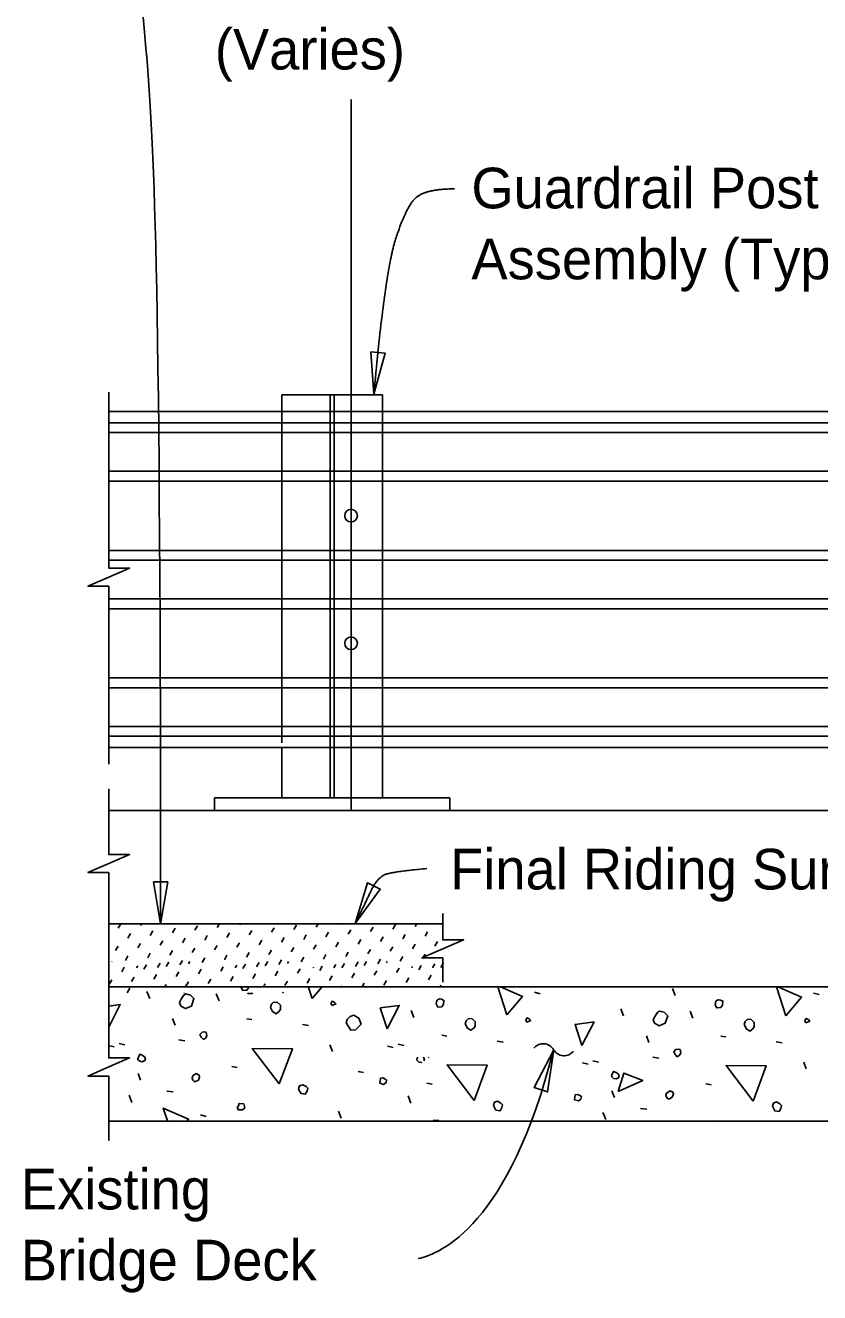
# Model space of a CAD drawing. Extents: x 21526.6 to 21598.7, y 56118.1 to 56155.9.
# Drawn here: x 21526.83 to 21530.77, y 56132.82 to 56139.11 of the extents above; entities that cross this region are included whole.
import ezdxf

# ---------------------------------------------------------------- set-up
doc = ezdxf.new("R2010")
doc.units = 0
for name, color, linetype in [('AdhocPoint_dp', 7, 'Continuous'), ('Border', 7, 'Continuous'), ('Patterning', 7, 'Continuous'), ('PlotBorder_dp', 7, 'Continuous'), ('SheetBorder_dp', 7, 'Continuous'), ('TextMisc', 7, 'Continuous')]:
    doc.layers.add(name, color=color, linetype=linetype)

msp = doc.modelspace()

# ---------------------------------------------------------------- linework, layer by layer
at = {"layer": 'AdhocPoint_dp'}
for p, q in [((21527.2426, 56135.21), (21535.6096, 56135.21)), ((21528.9006, 56134.6484), (21527.2426, 56134.6484)), ((21535.6096, 56134.335), (21527.2426, 56134.335)), ((21527.2426, 56133.6684), (21535.6096, 56133.6684))]:
    msp.add_line(p, q, dxfattribs=at)
at = {"layer": 'Patterning'}
for p, q in [((21528.4455, 56138.7381), (21528.4455, 56135.2123)), ((21527.2896, 56134.6259), (21527.3025, 56134.6483)), ((21527.4002, 56134.6388), (21527.4057, 56134.6484)), ((21527.5597, 56134.603), (21527.5726, 56134.6254)), ((21527.6703, 56134.6159), (21527.6833, 56134.6383)), ((21527.7809, 56134.6289), (21527.7922, 56134.6484)), ((21527.8916, 56134.6419), (21527.8953, 56134.6484)), ((21528.051, 56134.606), (21528.064, 56134.6284)), ((21528.1617, 56134.619), (21528.1746, 56134.6413)), ((21528.2723, 56134.6319), (21528.2818, 56134.6484)), ((21528.3829, 56134.6449), (21528.3849, 56134.6484)), ((21528.5424, 56134.609), (21528.5553, 56134.6314)), ((21528.653, 56134.622), (21528.666, 56134.6444)), ((21528.7637, 56134.6349), (21528.7714, 56134.6484)), ((21528.8743, 56134.6479), (21528.8745, 56134.6484)), ((21527.3384, 56134.577), (21527.3514, 56134.5994)), ((21527.449, 56134.59), (21527.462, 56134.6124)), ((21527.4979, 56134.5412), (21527.5108, 56134.5636)), ((21527.6085, 56134.5541), (21527.6215, 56134.5765)), ((21527.7191, 56134.5671), (21527.7321, 56134.5895)), ((21527.8298, 56134.5801), (21527.8427, 56134.6025)), ((21527.9404, 56134.593), (21527.9534, 56134.6154)), ((21527.9892, 56134.5442), (21528.0022, 56134.5666)), ((21528.0999, 56134.5572), (21528.1128, 56134.5795)), ((21528.2105, 56134.5701), (21528.2235, 56134.5925)), ((21528.3211, 56134.5831), (21528.3341, 56134.6055)), ((21528.4318, 56134.596), (21528.4447, 56134.6184)), ((21528.4806, 56134.5472), (21528.4936, 56134.5696)), ((21528.5912, 56134.5602), (21528.6042, 56134.5826)), ((21528.7019, 56134.5731), (21528.7148, 56134.5955)), ((21528.8125, 56134.5861), (21528.8254, 56134.6085)), ((21527.2766, 56134.5152), (21527.2896, 56134.5376)), ((21527.3872, 56134.5282), (21527.4002, 56134.5506)), ((21527.4361, 56134.4794), (21527.449, 56134.5018)), ((21527.5467, 56134.4923), (21527.5597, 56134.5147)), ((21527.6573, 56134.5053), (21527.6703, 56134.5277)), ((21527.768, 56134.5183), (21527.7809, 56134.5407)), ((21527.8786, 56134.5312), (21527.8916, 56134.5536)), ((21527.9274, 56134.4824), (21527.9404, 56134.5048)), ((21528.0381, 56134.4954), (21528.051, 56134.5177)), ((21528.1487, 56134.5083), (21528.1617, 56134.5307)), ((21528.2593, 56134.5213), (21528.2723, 56134.5437)), ((21528.37, 56134.5342), (21528.3829, 56134.5566)), ((21528.4188, 56134.4854), (21528.4318, 56134.5078)), ((21528.5294, 56134.4984), (21528.5424, 56134.5208)), ((21528.6401, 56134.5113), (21528.653, 56134.5337)), ((21528.7507, 56134.5243), (21528.7637, 56134.5467)), ((21528.8613, 56134.5373), (21528.8743, 56134.5597)), ((21527.2583, 56134.4585), (21527.2592, 56134.46)), ((21527.3254, 56134.4664), (21527.3384, 56134.4888)), ((21527.3811, 56134.4294), (21527.3872, 56134.44)), ((21527.4178, 56134.4226), (21527.4307, 56134.445)), ((21527.4849, 56134.4305), (21527.4979, 56134.4529)), ((21527.5284, 56134.4356), (21527.5413, 56134.458)), ((21527.5955, 56134.4435), (21527.6085, 56134.4659)), ((21527.639, 56134.4486), (21527.6457, 56134.46)), ((21527.7062, 56134.4565), (21527.7191, 56134.4789)), ((21527.8168, 56134.4694), (21527.8298, 56134.4918)), ((21527.8707, 56134.4294), (21527.8786, 56134.443)), ((21527.9091, 56134.4257), (21527.9221, 56134.4481)), ((21527.9763, 56134.4336), (21527.9892, 56134.4559)), ((21528.0198, 56134.4386), (21528.0321, 56134.46)), ((21528.0869, 56134.4465), (21528.0999, 56134.4689)), ((21528.1304, 56134.4516), (21528.1353, 56134.46)), ((21528.1975, 56134.4595), (21528.2105, 56134.4819)), ((21528.2899, 56134.4157), (21528.3028, 56134.4381)), ((21528.3082, 56134.4724), (21528.3211, 56134.4948)), ((21528.3603, 56134.4294), (21528.37, 56134.446)), ((21528.4005, 56134.4287), (21528.4134, 56134.4511)), ((21528.4676, 56134.4366), (21528.4806, 56134.459)), ((21528.5111, 56134.4416), (21528.5218, 56134.46)), ((21528.5783, 56134.4495), (21528.5912, 56134.4719)), ((21528.6217, 56134.4546), (21528.6249, 56134.46)), ((21528.6889, 56134.4625), (21528.7019, 56134.4849)), ((21528.7812, 56134.4187), (21528.7942, 56134.4411)), ((21528.7995, 56134.4755), (21528.8125, 56134.4979)), ((21528.8499, 56134.4294), (21528.8613, 56134.449)), ((21528.8918, 56134.4317), (21528.9048, 56134.4541)), ((21528.9102, 56134.4884), (21528.9103, 56134.4886)), ((21527.3071, 56134.4097), (21527.3201, 56134.4321)), ((21527.356, 56134.3608), (21527.3689, 56134.3832)), ((21527.4666, 56134.3738), (21527.4796, 56134.3962)), ((21527.5772, 56134.3868), (21527.5902, 56134.4092)), ((21527.6879, 56134.3997), (21527.7008, 56134.4221)), ((21527.7676, 56134.4294), (21527.768, 56134.43)), ((21527.7985, 56134.4127), (21527.8114, 56134.4351)), ((21527.8473, 56134.3639), (21527.8603, 56134.3863)), ((21527.958, 56134.3768), (21527.9709, 56134.3992)), ((21528.0686, 56134.3898), (21528.0815, 56134.4122)), ((21528.1792, 56134.4028), (21528.1922, 56134.4251)), ((21528.2281, 56134.3539), (21528.241, 56134.3763)), ((21528.2572, 56134.4294), (21528.2593, 56134.433)), ((21528.3387, 56134.3669), (21528.3516, 56134.3893)), ((21528.4493, 56134.3798), (21528.4623, 56134.4022)), ((21528.56, 56134.3928), (21528.5729, 56134.4152)), ((21528.6706, 56134.4058), (21528.6835, 56134.4282)), ((21528.7194, 56134.3569), (21528.7324, 56134.3793)), ((21528.7468, 56134.4294), (21528.7507, 56134.4361)), ((21528.8301, 56134.3699), (21528.843, 56134.3923)), ((21527.2453, 56134.3479), (21527.2583, 56134.3703)), ((21527.3349, 56134.3055), (21527.3478, 56134.3279)), ((21527.4465, 56134.2767), (21527.4324, 56134.3121)), ((21527.5212, 56134.335), (21527.5284, 56134.3474)), ((21527.6261, 56134.3379), (21527.639, 56134.3603)), ((21527.7367, 56134.3509), (21527.7497, 56134.3733)), ((21527.9077, 56134.335), (21527.9091, 56134.3374)), ((21528.0109, 56134.335), (21528.0198, 56134.3504)), ((21528.1174, 56134.341), (21528.1304, 56134.3633)), ((21528.3974, 56134.335), (21528.4005, 56134.3404)), ((21528.5005, 56134.335), (21528.5111, 56134.3534)), ((21528.6088, 56134.344), (21528.6217, 56134.3664)), ((21528.887, 56134.335), (21528.8918, 56134.3435)), ((21530.0545, 56134.292), (21530.0403, 56134.3273)), ((21527.6176, 56134.3044), (21527.6179, 56134.305)), ((21527.7906, 56134.265), (21527.7765, 56134.3003)), ((21528.1072, 56134.3044), (21528.1093, 56134.308)), ((21529.3562, 56134.3079), (21529.3845, 56134.3008)), ((21530.7409, 56134.3043), (21530.7691, 56134.2973)), ((21528.7575, 56134.183), (21528.7434, 56134.2183)), ((21529.7981, 56134.1912), (21529.784, 56134.2266)), ((21530.1422, 56134.1795), (21530.1281, 56134.2148)), ((21527.572, 56134.1442), (21527.5597, 56134.1777)), ((21527.9285, 56134.1766), (21527.9533, 56134.1731)), ((21528.2043, 56134.1483), (21528.2343, 56134.143)), ((21527.5909, 56134.0723), (21527.6209, 56134.067)), ((21528.8954, 56134.0946), (21528.9202, 56134.0911)), ((21529.1712, 56134.0663), (21529.2012, 56134.061)), ((21529.9236, 56134.0586), (21529.9113, 56134.0922)), ((21530.2801, 56134.0911), (21530.3049, 56134.0875)), ((21530.5559, 56134.0628), (21530.5859, 56134.0575)), ((21527.2421, 56134.044), (21527.2704, 56134.037)), ((21527.2945, 56134.054), (21527.3228, 56134.0469)), ((21528.3528, 56134.014), (21528.3404, 56134.0476)), ((21528.6268, 56134.0405), (21528.6551, 56134.0334)), ((21528.6792, 56134.0505), (21528.7075, 56134.0434)), ((21527.8543, 56133.9397), (21527.8808, 56133.9344)), ((21529.5937, 56133.9585), (21529.622, 56133.9514)), ((21529.6461, 56133.9685), (21529.6744, 56133.9614)), ((21529.9425, 56133.9868), (21529.9725, 56133.9815)), ((21530.7044, 56133.9284), (21530.692, 56133.962)), ((21527.4006, 56133.8714), (21527.3882, 56133.905)), ((21528.48, 56133.915), (21528.5066, 56133.9097)), ((21527.5308, 56133.8177), (21527.5626, 56133.8142)), ((21528.8212, 56133.8577), (21528.8477, 56133.8524)), ((21529.7522, 56133.7859), (21529.7398, 56133.8195)), ((21530.2059, 56133.8542), (21530.2324, 56133.8489)), ((21527.3581, 56133.7618), (21527.344, 56133.7972)), ((21528.7428, 56133.7583), (21528.7287, 56133.7936)), ((21527.6987, 56133.6993), (21527.727, 56133.6922)), ((21528.397, 56133.6834), (21528.3828, 56133.7188)), ((21529.7097, 56133.6763), (21529.6956, 56133.7116)), ((21529.8824, 56133.7322), (21529.9142, 56133.7287))]:
    msp.add_line(p, q, dxfattribs=at)
for points in [[(21527.9005, 56134.3317), (21527.9091, 56134.3163), (21527.9285, 56134.318), (21527.9373, 56134.3304), (21527.9375, 56134.3317)], [(21528.252, 56134.2774), (21528.2343, 56134.3317)], [(21528.298, 56134.3317), (21528.252, 56134.2774)], [(21529.2189, 56134.1954), (21529.1735, 56134.335)], [(21529.1874, 56134.335), (21529.2967, 56134.2873), (21529.2189, 56134.1954)], [(21530.6036, 56134.1918), (21530.557, 56134.335)], [(21530.564, 56134.335), (21530.6814, 56134.2838), (21530.6036, 56134.1918)], [(21527.6003, 56134.2396), (21527.6233, 56134.2272), (21527.6534, 56134.2396), (21527.6657, 56134.2767), (21527.6481, 56134.2944), (21527.6251, 56134.2997), (21527.6145, 56134.2927), (21527.6021, 56134.2732), (21527.5933, 56134.2573), (21527.6003, 56134.2396)], [(21527.9326, 56134.3044), (21527.9336, 56134.302), (21527.9312, 56134.3044)], [(21527.9336, 56134.302), (21527.9548, 56134.302), (21527.9572, 56134.3044)], [(21528.0452, 56134.2332), (21528.0558, 56134.212), (21528.0735, 56134.2014), (21528.0876, 56134.212), (21528.0947, 56134.2226), (21528.0947, 56134.2438), (21528.0788, 56134.2597), (21528.0593, 56134.2579), (21528.0505, 56134.2491), (21528.0452, 56134.2332)], [(21528.351, 56134.242), (21528.3704, 56134.2509), (21528.3634, 56134.2579), (21528.351, 56134.2632), (21528.3457, 56134.2509), (21528.351, 56134.242)], [(21528.8671, 56134.2502), (21528.876, 56134.2343), (21528.8954, 56134.236), (21528.9043, 56134.2484), (21528.906, 56134.2678), (21528.8937, 56134.2731), (21528.8848, 56134.2749), (21528.8742, 56134.2714), (21528.8707, 56134.2678), (21528.8671, 56134.2502)], [(21530.2518, 56134.2466), (21530.2607, 56134.2307), (21530.2801, 56134.2325), (21530.2889, 56134.2449), (21530.2907, 56134.2643), (21530.2783, 56134.2696), (21530.2695, 56134.2714), (21530.2589, 56134.2678), (21530.2554, 56134.2643), (21530.2518, 56134.2466)], [(21527.2426, 56134.2391), (21527.2998, 56134.2467), (21527.2427, 56134.1358)], [(21528.4217, 56134.1572), (21528.4447, 56134.12), (21528.4677, 56134.1218), (21528.4765, 56134.1306), (21528.496, 56134.1501), (21528.4836, 56134.1801), (21528.4588, 56134.1943), (21528.4412, 56134.1872), (21528.427, 56134.1731), (21528.4217, 56134.1572)], [(21528.6244, 56134.1265), (21528.5908, 56134.2308), (21528.6845, 56134.2432), (21528.6244, 56134.1265)], [(21529.9519, 56134.1541), (21529.9749, 56134.1417), (21530.005, 56134.1541), (21530.0173, 56134.1912), (21529.9997, 56134.2089), (21529.9767, 56134.2142), (21529.9661, 56134.2071), (21529.9537, 56134.1877), (21529.9449, 56134.1718), (21529.9519, 56134.1541)], [(21529.0121, 56134.1512), (21529.0227, 56134.13), (21529.0404, 56134.1194), (21529.0545, 56134.13), (21529.0616, 56134.1406), (21529.0616, 56134.1618), (21529.0457, 56134.1777), (21529.0262, 56134.1759), (21529.0174, 56134.1671), (21529.0121, 56134.1512)], [(21529.3179, 56134.16), (21529.3374, 56134.1689), (21529.3303, 56134.1759), (21529.3179, 56134.1812), (21529.3126, 56134.1689), (21529.3179, 56134.16)], [(21529.5913, 56134.0445), (21529.5577, 56134.1488), (21529.6514, 56134.1612), (21529.5913, 56134.0445)], [(21530.3968, 56134.1476), (21530.4074, 56134.1264), (21530.4251, 56134.1158), (21530.4392, 56134.1264), (21530.4463, 56134.137), (21530.4463, 56134.1582), (21530.4304, 56134.1742), (21530.4109, 56134.1724), (21530.4021, 56134.1635), (21530.3968, 56134.1476)], [(21530.7026, 56134.1565), (21530.722, 56134.1653), (21530.715, 56134.1724), (21530.7026, 56134.1777), (21530.6973, 56134.1653), (21530.7026, 56134.1565)], [(21527.7022, 56134.0847), (21527.7128, 56134.0741), (21527.7234, 56134.0811), (21527.7305, 56134.0918), (21527.727, 56134.1094), (21527.7181, 56134.1112), (21527.7058, 56134.1094), (21527.6952, 56134.0988), (21527.7022, 56134.0847)], [(21527.397, 56133.9656), (21527.4094, 56133.9638), (21527.4218, 56133.9692), (21527.4253, 56133.9798), (21527.42, 56133.9886), (21527.4094, 56133.9957), (21527.397, 56134.001), (21527.39, 56133.9868), (21527.3864, 56133.9762), (21527.397, 56133.9656)], [(21528.0894, 56133.8531), (21527.955, 56134.0299), (21528.1548, 56134.0281), (21528.0894, 56133.8531)], [(21530.0538, 56133.9991), (21530.0644, 56133.9885), (21530.075, 56133.9956), (21530.0821, 56134.0062), (21530.0786, 56134.0239), (21530.0697, 56134.0257), (21530.0574, 56134.0239), (21530.0468, 56134.0133), (21530.0538, 56133.9991)], [(21528.776, 56133.9861), (21528.7746, 56133.9833), (21528.7711, 56133.9727), (21528.7817, 56133.9621)], [(21528.7817, 56133.9621), (21528.7941, 56133.9603), (21528.796, 56133.9611)], [(21528.8073, 56133.9681), (21528.81, 56133.9762), (21528.8047, 56133.9851), (21528.8031, 56133.9861)], [(21528.8302, 56133.9823), (21528.8314, 56133.9861)], [(21529.0563, 56133.7711), (21528.9219, 56133.9479), (21529.1217, 56133.9461), (21529.0563, 56133.7711)], [(21530.441, 56133.7676), (21530.3066, 56133.9443), (21530.5064, 56133.9426), (21530.441, 56133.7676)], [(21527.6669, 56133.8655), (21527.6739, 56133.8655), (21527.6881, 56133.8725), (21527.6934, 56133.8885), (21527.6916, 56133.8973), (21527.6775, 56133.9044), (21527.6598, 56133.8938), (21527.6563, 56133.8832), (21527.6598, 56133.8725), (21527.6669, 56133.8655)], [(21528.5879, 56133.8566), (21528.6073, 56133.8513), (21528.6197, 56133.8602), (21528.6215, 56133.8725), (21528.6179, 56133.8761), (21528.6038, 56133.8832), (21528.5914, 56133.8814), (21528.5897, 56133.869), (21528.5879, 56133.8566)], [(21529.7486, 56133.8801), (21529.761, 56133.8783), (21529.7734, 56133.8836), (21529.7769, 56133.8942), (21529.7716, 56133.9031), (21529.761, 56133.9101), (21529.7486, 56133.9154), (21529.7416, 56133.9013), (21529.738, 56133.8907), (21529.7486, 56133.8801)], [(21529.771, 56133.8153), (21529.7993, 56133.9072), (21529.893, 56133.8701), (21529.771, 56133.8153)], [(21528.1884, 56133.8213), (21528.1972, 56133.8054), (21528.2184, 56133.8018), (21528.2273, 56133.8177), (21528.2308, 56133.8319), (21528.222, 56133.8407), (21528.206, 56133.8496), (21528.1901, 56133.8443), (21528.1848, 56133.8284), (21528.1884, 56133.8213)], [(21530.0185, 56133.7799), (21530.0255, 56133.7799), (21530.0397, 56133.787), (21530.045, 56133.8029), (21530.0432, 56133.8118), (21530.0291, 56133.8188), (21530.0114, 56133.8082), (21530.0079, 56133.7976), (21530.0114, 56133.787), (21530.0185, 56133.7799)], [(21527.8861, 56133.7241), (21527.9073, 56133.7241), (21527.9179, 56133.7347), (21527.9126, 56133.7541), (21527.8896, 56133.7559), (21527.8861, 56133.7453), (21527.8808, 56133.7364), (21527.8861, 56133.7241), (21527.8825, 56133.7276)], [(21529.1553, 56133.7393), (21529.1641, 56133.7234), (21529.1853, 56133.7198), (21529.1942, 56133.7357), (21529.1977, 56133.7499), (21529.1889, 56133.7587), (21529.173, 56133.7676), (21529.1571, 56133.7623), (21529.1518, 56133.7464), (21529.1553, 56133.7393)], [(21529.5548, 56133.7746), (21529.5742, 56133.7693), (21529.5866, 56133.7782), (21529.5884, 56133.7905), (21529.5849, 56133.7941), (21529.5707, 56133.8012), (21529.5583, 56133.7994), (21529.5566, 56133.787), (21529.5548, 56133.7746)], [(21530.54, 56133.7357), (21530.5488, 56133.7198), (21530.57, 56133.7163), (21530.5789, 56133.7322), (21530.5824, 56133.7464), (21530.5736, 56133.7552), (21530.5576, 56133.764), (21530.5417, 56133.7587), (21530.5364, 56133.7428), (21530.54, 56133.7357)], [(21527.536, 56133.665), (21527.5137, 56133.7335), (21527.6392, 56133.6787), (21527.6276, 56133.665)], [(21528.8805, 56133.6684), (21528.8795, 56133.6721), (21528.8565, 56133.6739), (21528.8547, 56133.6684)], [(21530.2643, 56133.6684), (21530.2642, 56133.6686), (21530.2412, 56133.6703), (21530.2406, 56133.6684)]]:
    msp.add_lwpolyline(points, dxfattribs=at)
at = {"layer": 'PlotBorder_dp'}
for points in [[(21528.5583, 56137.2748), (21528.614, 56137.4786), (21528.5438, 56137.4856)], [(21527.5005, 56134.6471), (21527.5357, 56134.8553), (21527.4652, 56134.8553)], [(21528.466, 56134.6497), (21528.5907, 56134.8202), (21528.5275, 56134.8517)], [(21529.4513, 56134.0231), (21529.4208, 56133.8141), (21529.3537, 56133.8358)]]:
    msp.add_lwpolyline(points, close=True, dxfattribs=at)
for points in [[(21527.2427, 56135.4395), (21527.2427, 56136.3228), (21527.1393, 56136.3228), (21527.2427, 56136.3678), (21527.346, 56136.4128), (21527.2427, 56136.4128), (21527.2427, 56137.2857)], [(21527.2427, 56134.3351), (21527.2427, 56134.9021), (21527.1393, 56134.9021), (21527.2427, 56134.9471), (21527.346, 56134.9921), (21527.2427, 56134.9921), (21527.2427, 56135.3182)], [(21528.9006, 56134.3576), (21528.9006, 56134.4784), (21528.7973, 56134.4784), (21528.9006, 56134.5234), (21529.004, 56134.5684), (21528.9006, 56134.5684), (21528.9006, 56134.699)], [(21527.2427, 56133.5727), (21527.2427, 56133.8927), (21527.1393, 56133.8927), (21527.2427, 56133.9377), (21527.346, 56133.9827), (21527.2427, 56133.9827), (21527.2427, 56134.3351)]]:
    msp.add_lwpolyline(points, dxfattribs=at)
for centre, start, end in [((21529.3989, 56133.9934), 30.00813, 141.73535), ((21529.5022, 56134.053), 210.00813, 321.73535)]:
    msp.add_arc(centre, 0.0596, start, end, dxfattribs=at)
for points, degree in [([(21527.7124, 56139.6659), (21527.3412, 56139.6133), (21527.4415, 56139.2069), (21527.5005, 56137.7639), (21527.5005, 56134.6471)], 3), ([(21528.9594, 56138.2938), (21528.8192, 56138.2938), (21528.7196, 56138.2097), (21528.6137, 56137.8793), (21528.5583, 56137.2748)], 2), ([(21528.8223, 56134.922), (21528.6486, 56134.9066), (21528.5744, 56134.8752), (21528.5088, 56134.7353), (21528.466, 56134.6497)], 2), ([(21529.4505, 56134.0233), (21529.2298, 56133.1495), (21528.889, 56133.0123), (21528.7791, 56132.9866)], 3)]:
    msp.add_open_spline(points, degree=degree, dxfattribs=at)
at = {"layer": 'SheetBorder_dp'}
for p, q in [((21528.3413, 56135.2726), (21528.3413, 56137.2726)), ((21528.3622, 56135.2726), (21528.3622, 56137.2726)), ((21528.1017, 56137.1892), (21528.1017, 56135.5456)), ((21528.6017, 56137.1892), (21528.6017, 56135.5225))]:
    msp.add_line(p, q, dxfattribs=at)
at = {"layer": 'TextMisc'}
for p, q in [((21528.6017, 56137.2726), (21528.1017, 56137.2726)), ((21528.1017, 56137.2726), (21528.1017, 56137.1892)), ((21528.6017, 56137.2726), (21528.6017, 56137.1892)), ((21534.2788, 56137.1892), (21527.2426, 56137.1892)), ((21527.2426, 56137.1336), (21534.2788, 56137.1336)), ((21527.2426, 56137.0854), (21534.2788, 56137.0854)), ((21527.2426, 56136.8926), (21534.2788, 56136.8926)), ((21527.2426, 56136.8444), (21534.2788, 56136.8444)), ((21527.2426, 56136.5004), (21534.2788, 56136.5004)), ((21527.2426, 56136.4522), (21534.2788, 56136.4522)), ((21527.2426, 56136.2594), (21534.2788, 56136.2594)), ((21527.2426, 56136.2112), (21534.2788, 56136.2112)), ((21527.2426, 56135.8673), (21534.2788, 56135.8673)), ((21527.2426, 56135.8191), (21534.2788, 56135.8191)), ((21527.2426, 56135.6262), (21534.2788, 56135.6262)), ((21527.2426, 56135.578), (21534.2788, 56135.578)), ((21534.2788, 56135.5225), (21527.2426, 56135.5225)), ((21528.1017, 56135.5225), (21528.1017, 56135.2726)), ((21528.6017, 56135.5225), (21528.6017, 56135.2726)), ((21528.6017, 56135.4392), (21528.6017, 56135.2726)), ((21527.7684, 56135.2726), (21528.9351, 56135.2726)), ((21527.7684, 56135.2101), (21527.7684, 56135.2726)), ((21528.6017, 56135.2726), (21528.1017, 56135.2726)), ((21528.9351, 56135.2726), (21528.9351, 56135.2101)), ((21527.7684, 56135.2101), (21528.9351, 56135.2101))]:
    msp.add_line(p, q, dxfattribs=at)
for centre in [(21528.4455, 56136.6725), (21528.4455, 56136.0393)]:
    msp.add_circle(centre, 0.0312, dxfattribs=at)

# ---------------------------------------------------------------- texts
at = {"layer": 'Border'}
msp.add_text('Final Riding Surface', height=0.2016, dxfattribs=at).set_placement((21528.9369, 56134.8183))
at = {"layer": 'PlotBorder_dp'}
for s, p in [('(Varies)', (21527.7694, 56138.8861)), ('Guardrail Post ', (21529.0427, 56138.1973)), ('Assembly (Typ.)', (21529.0427, 56137.8453)), ('Existing ', (21526.8068, 56133.2307)), ('Bridge Deck', (21526.8068, 56132.8787))]:
    msp.add_text(s, height=0.2016, dxfattribs=at).set_placement(p)

doc.saveas('drawing.dxf')
